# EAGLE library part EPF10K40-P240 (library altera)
EPF10K40 FLEX 10K family
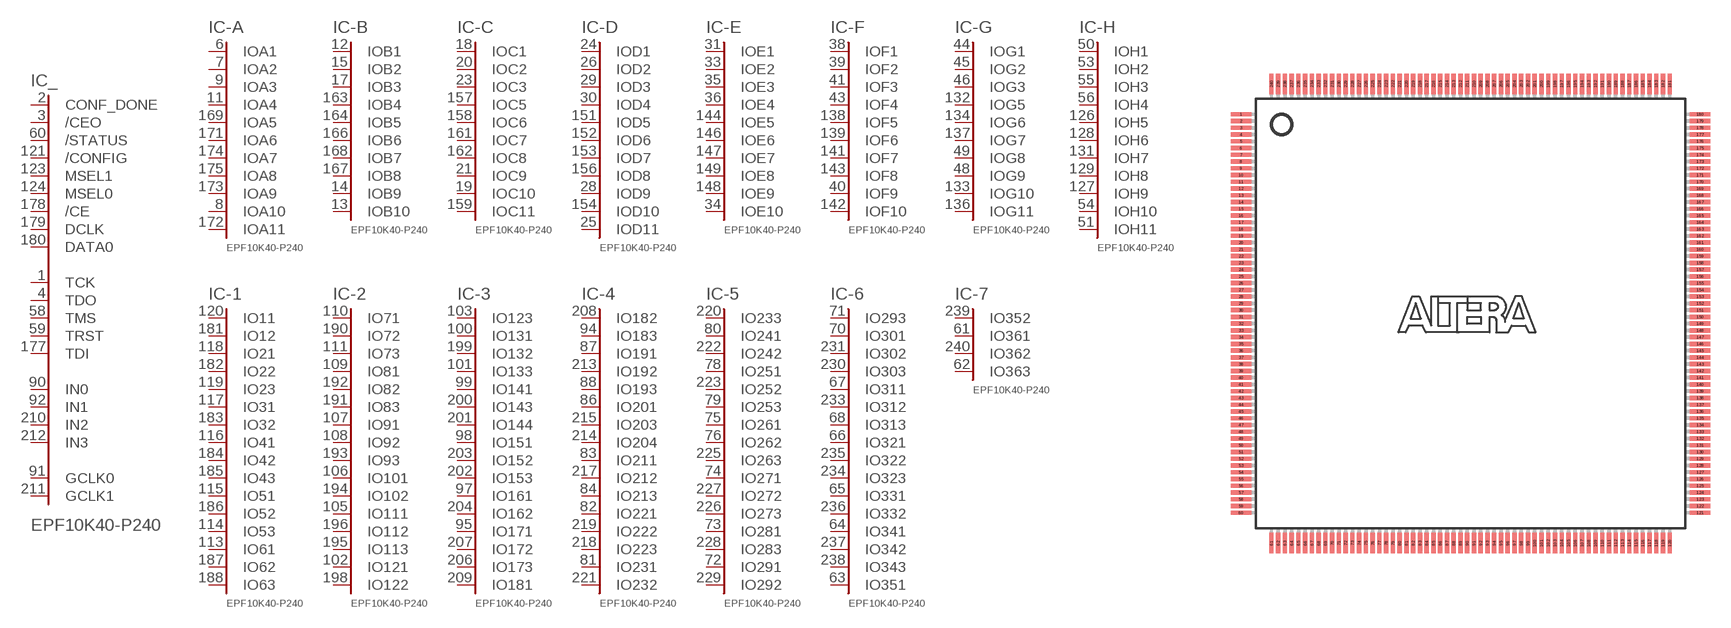
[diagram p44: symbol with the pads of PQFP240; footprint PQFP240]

Designator prefix IC; gates _=100R240C -A=A11 -B=B10 -C=C11_4 -D=D11 -E=E10 -F=F10 -G=G11 -H=H11 -1=63-40 -2=122-40 -3=181-40 -4=232-40 -5=292-40 -6=351-40 -7=363-40 1=VCCINT 2=VCCINT 3=VCCINT 4=VCCINT 5=VCCINT 6=VCCINT 7=VCCINT 8=VCCINT 9=VCCINT 10=VCCINT 11=VCCINT 12=VCCINT 13=VCCINT 14=VCCINT 15=VCCINT 16=VCCINT 17=VCCINT 18=VCCINT 19=VCCINT 20=GNDINT 21=GNDINT 22=GNDINT 23=GNDINT 24=GNDINT 25=GNDINT 26=GNDINT 27=GNDINT 28=GNDINT 29=GNDINT 30=GNDINT 31=GNDINT 32=GNDINT 33=GNDINT 34=GNDINT 35=GNDINT 36=GNDINT 37=GNDINT

## EPF10K40-P240 (MPN: EPF10K40RC240-4N; OC_FARNELL: unknown; OC_NEWARK: 51R9017)  [PQFP240]
1  _:TCK
2  _:CONF_DONE  in
3  _:/CEO  in
4  _:TDO
5  1:VCC  pwr
6  -A:IOA1
7  -A:IOA2
8  -A:IOA10
9  -A:IOA3
10  20:GND  pwr
11  -A:IOA4
12  -B:IOB1
13  -B:IOB10
14  -B:IOB9
15  -B:IOB2
16  2:VCC  pwr
17  -B:IOB3
18  -C:IOC1
19  -C:IOC10
20  -C:IOC2
21  -C:IOC9
22  21:GND  pwr
23  -C:IOC3
24  -D:IOD1
25  -D:IOD11
26  -D:IOD2
27  3:VCC  pwr
28  -D:IOD9
29  -D:IOD3
30  -D:IOD4
31  -E:IOE1
32  22:GND  pwr
33  -E:IOE2
34  -E:IOE10
35  -E:IOE3
36  -E:IOE4
37  4:VCC  pwr
38  -F:IOF1
39  -F:IOF2
40  -F:IOF9
41  -F:IOF3
42  23:GND  pwr
43  -F:IOF4
44  -G:IOG1
45  -G:IOG2
46  -G:IOG3
47  5:VCC  pwr
48  -G:IOG9
49  -G:IOG8
50  -H:IOH1
51  -H:IOH11
52  24:GND  pwr
53  -H:IOH2
54  -H:IOH10
55  -H:IOH3
56  -H:IOH4
57  6:VCC  pwr
58  _:TMS
59  _:TRST
60  _:/STATUS  in
61  -7:IO361
62  -7:IO363
63  -6:IO351
64  -6:IO341
65  -6:IO331
66  -6:IO321
67  -6:IO311
68  -6:IO313
69  25:GND  pwr
70  -6:IO301
71  -6:IO293
72  -5:IO291
73  -5:IO281
74  -5:IO271
75  -5:IO261
76  -5:IO262
77  7:VCC  pwr
78  -5:IO251
79  -5:IO253
80  -5:IO241
81  -4:IO231
82  -4:IO221
83  -4:IO211
84  -4:IO213
85  26:GND  pwr
86  -4:IO201
87  -4:IO191
88  -4:IO193
89  8:VCC  pwr
90  _:IN0  in
91  _:GCLK0  in
92  _:IN1  in
93  27:GND  pwr
94  -4:IO183
95  -3:IO171
96  9:VCC  pwr
97  -3:IO161
98  -3:IO151
99  -3:IO141
100  -3:IO131
101  -3:IO133
102  -2:IO121
103  -3:IO123
104  28:GND  pwr
105  -2:IO111
106  -2:IO101
107  -2:IO91
108  -2:IO92
109  -2:IO81
110  -2:IO71
111  -2:IO73
112  10:VCC  pwr
113  -1:IO61
114  -1:IO53
115  -1:IO51
116  -1:IO41
117  -1:IO31
118  -1:IO21
119  -1:IO23
120  -1:IO11
121  _:/CONFIG  in
122  11:VCC  pwr
123  _:MSEL1  in
124  _:MSEL0  in
125  29:GND  pwr
126  -H:IOH5
127  -H:IOH9
128  -H:IOH6
129  -H:IOH8
130  12:VCC  pwr
131  -H:IOH7
132  -G:IOG5
133  -G:IOG10
134  -G:IOG6
135  30:GND  pwr
136  -G:IOG11
137  -G:IOG7
138  -F:IOF5
139  -F:IOF6
140  13:VCC  pwr
141  -F:IOF7
142  -F:IOF10
143  -F:IOF8
144  -E:IOE5
145  31:GND  pwr
146  -E:IOE6
147  -E:IOE7
148  -E:IOE9
149  -E:IOE8
150  14:VCC  pwr
151  -D:IOD5
152  -D:IOD6
153  -D:IOD7
154  -D:IOD10
155  32:GND  pwr
156  -D:IOD8
157  -C:IOC5
158  -C:IOC6
159  -C:IOC11
160  15:VCC  pwr
161  -C:IOC7
162  -C:IOC8
163  -B:IOB4
164  -B:IOB5
165  33:GND  pwr
166  -B:IOB6
167  -B:IOB8
168  -B:IOB7
169  -A:IOA5
170  16:VCC  pwr
171  -A:IOA6
172  -A:IOA11
173  -A:IOA9
174  -A:IOA7
175  -A:IOA8
176  34:GND  pwr
177  _:TDI
178  _:/CE  in
179  _:DCLK  in
180  _:DATA0  in
181  -1:IO12
182  -1:IO22
183  -1:IO32
184  -1:IO42
185  -1:IO43
186  -1:IO52
187  -1:IO62
188  -1:IO63
189  17:VCC  pwr
190  -2:IO72
191  -2:IO83
192  -2:IO82
193  -2:IO93
194  -2:IO102
195  -2:IO113
196  -2:IO112
197  35:GND  pwr
198  -2:IO122
199  -3:IO132
200  -3:IO143
201  -3:IO144
202  -3:IO153
203  -3:IO152
204  -3:IO162
205  18:VCC  pwr
206  -3:IO173
207  -3:IO172
208  -4:IO182
209  -3:IO181
210  _:IN2  in
211  _:GCLK1  in
212  _:IN3  in
213  -4:IO192
214  -4:IO204
215  -4:IO203
216  36:GND  pwr
217  -4:IO212
218  -4:IO223
219  -4:IO222
220  -5:IO233
221  -4:IO232
222  -5:IO242
223  -5:IO252
224  19:VCC  pwr
225  -5:IO263
226  -5:IO273
227  -5:IO272
228  -5:IO283
229  -5:IO292
230  -6:IO303
231  -6:IO302
232  37:GND  pwr
233  -6:IO312
234  -6:IO323
235  -6:IO322
236  -6:IO332
237  -6:IO342
238  -6:IO343
239  -7:IO352
240  -7:IO362

## Footprint PQFP240 (pad centres in mm)
Plastic Quad Flat Pack
smd 1.5 x 0.32: 1 -17,14.75; 2 -17,14.25; 3 -17,13.75; 4 -17,13.25; 5 -17,12.75; 6 -17,12.25; 7 -17,11.75; 8 -17,11.25; 9 -17,10.75; 10 -17,10.25; 11 -17,9.75; 12 -17,9.25; 13 -17,8.75; 14 -17,8.25; 15 -17,7.75; 16 -17,7.25; 17 -17,6.75; 18 -17,6.25; 19 -17,5.75; 20 -17,5.25; 21 -17,4.75; 22 -17,4.25; 23 -17,3.75; 24 -17,3.25; 25 -17,2.75; 26 -17,2.25; 27 -17,1.75; 28 -17,1.25; 29 -17,0.75; 30 -17,0.25; 31 -17,-0.25; 32 -17,-0.75; 33 -17,-1.25; 34 -17,-1.75; 35 -17,-2.25; 36 -17,-2.75; 37 -17,-3.25; 38 -17,-3.75; 39 -17,-4.25; 40 -17,-4.75; 41 -17,-5.25; 42 -17,-5.75; 43 -17,-6.25; 44 -17,-6.75; 45 -17,-7.25; 46 -17,-7.75; 47 -17,-8.25; 48 -17,-8.75; 49 -17,-9.25; 50 -17,-9.75; 51 -17,-10.25; 52 -17,-10.75; 53 -17,-11.25; 54 -17,-11.75; 55 -17,-12.25; 56 -17,-12.75; 57 -17,-13.25; 58 -17,-13.75; 59 -17,-14.25; 60 -17,-14.75; 121 17,-14.75; 122 17,-14.25; 123 17,-13.75; 124 17,-13.25; 125 17,-12.75; 126 17,-12.25; 127 17,-11.75; 128 17,-11.25; 129 17,-10.75; 130 17,-10.25; 131 17,-9.75; 132 17,-9.25; 133 17,-8.75; 134 17,-8.25; 135 17,-7.75; 136 17,-7.25; 137 17,-6.75; 138 17,-6.25; 139 17,-5.75; 140 17,-5.25; 141 17,-4.75; 142 17,-4.25; 143 17,-3.75; 144 17,-3.25; 145 17,-2.75; 146 17,-2.25; 147 17,-1.75; 148 17,-1.25; 149 17,-0.75; 150 17,-0.25; 151 17,0.25; 152 17,0.75; 153 17,1.25; 154 17,1.75; 155 17,2.25; 156 17,2.75; 157 17,3.25; 158 17,3.75; 159 17,4.25; 160 17,4.75; 161 17,5.25; 162 17,5.75; 163 17,6.25; 164 17,6.75; 165 17,7.25; 166 17,7.75; 167 17,8.25; 168 17,8.75; 169 17,9.25; 170 17,9.75; 171 17,10.25; 172 17,10.75; 173 17,11.25; 174 17,11.75; 175 17,12.25; 176 17,12.75; 177 17,13.25; 178 17,13.75; 179 17,14.25; 180 17,14.75
smd 0.32 x 1.5: 61 -14.75,-17; 62 -14.25,-17; 63 -13.75,-17; 64 -13.25,-17; 65 -12.75,-17; 66 -12.25,-17; 67 -11.75,-17; 68 -11.25,-17; 69 -10.75,-17; 70 -10.25,-17; 71 -9.75,-17; 72 -9.25,-17; 73 -8.75,-17; 74 -8.25,-17; 75 -7.75,-17; 76 -7.25,-17; 77 -6.75,-17; 78 -6.25,-17; 79 -5.75,-17; 80 -5.25,-17; 81 -4.75,-17; 82 -4.25,-17; 83 -3.75,-17; 84 -3.25,-17; 85 -2.75,-17; 86 -2.25,-17; 87 -1.75,-17; 88 -1.25,-17; 89 -0.75,-17; 90 -0.25,-17; 91 0.25,-17; 92 0.75,-17; 93 1.25,-17; 94 1.75,-17; 95 2.25,-17; 96 2.75,-17; 97 3.25,-17; 98 3.75,-17; 99 4.25,-17; 100 4.75,-17; 101 5.25,-17; 102 5.75,-17; 103 6.25,-17; 104 6.75,-17; 105 7.25,-17; 106 7.75,-17; 107 8.25,-17; 108 8.75,-17; 109 9.25,-17; 110 9.75,-17; 111 10.25,-17; 112 10.75,-17; 113 11.25,-17; 114 11.75,-17; 115 12.25,-17; 116 12.75,-17; 117 13.25,-17; 118 13.75,-17; 119 14.25,-17; 120 14.75,-17; 181 14.75,17; 182 14.25,17; 183 13.75,17; 184 13.25,17; 185 12.75,17; 186 12.25,17; 187 11.75,17; 188 11.25,17; 189 10.75,17; 190 10.25,17; 191 9.75,17; 192 9.25,17; 193 8.75,17; 194 8.25,17; 195 7.75,17; 196 7.25,17; 197 6.75,17; 198 6.25,17; 199 5.75,17; 200 5.25,17; 201 4.75,17; 202 4.25,17; 203 3.75,17; 204 3.25,17; 205 2.75,17; 206 2.25,17; 207 1.75,17; 208 1.25,17; 209 0.75,17; 210 0.25,17; 211 -0.25,17; 212 -0.75,17; 213 -1.25,17; 214 -1.75,17; 215 -2.25,17; 216 -2.75,17; 217 -3.25,17; 218 -3.75,17; 219 -4.25,17; 220 -4.75,17; 221 -5.25,17; 222 -5.75,17; 223 -6.25,17; 224 -6.75,17; 225 -7.25,17; 226 -7.75,17; 227 -8.25,17; 228 -8.75,17; 229 -9.25,17; 230 -9.75,17; 231 -10.25,17; 232 -10.75,17; 233 -11.25,17; 234 -11.75,17; 235 -12.25,17; 236 -12.75,17; 237 -13.25,17; 238 -13.75,17; 239 -14.25,17; 240 -14.75,17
